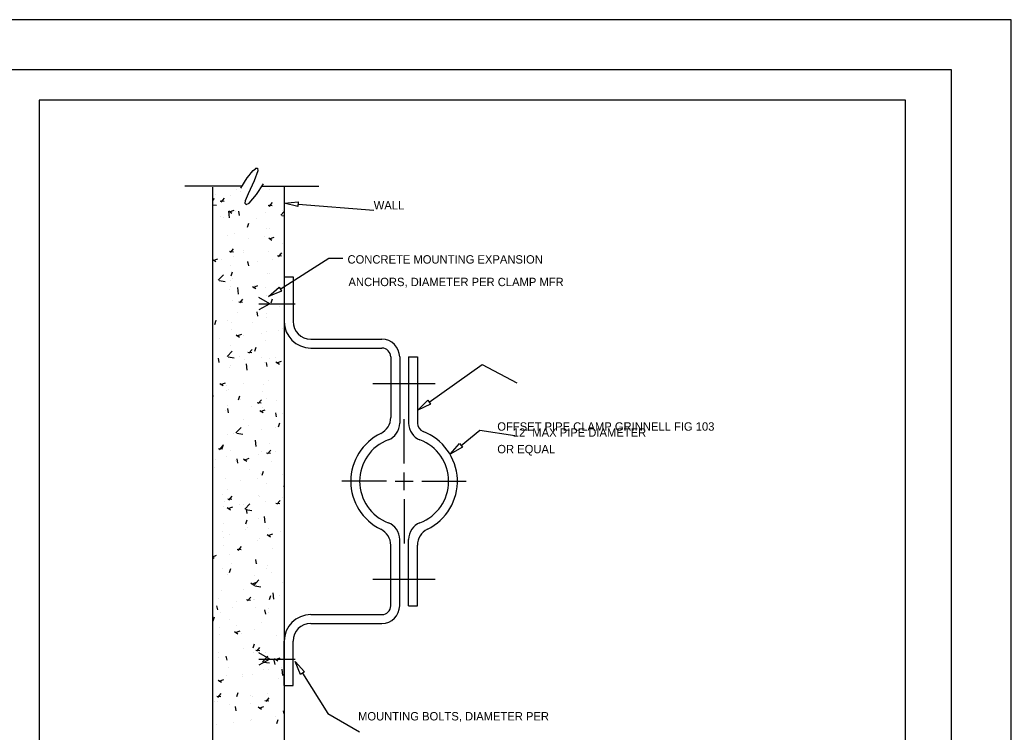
# Model space of a CAD drawing. Extents: x 2147138 to 2147698, y 2147153 to 2147515.
# Drawn here: x 2147555.6 to 2147697.7, y 2147412.9 to 2147515.1 of the extents above; entities that cross this region are included whole.
import ezdxf

# ---------------------------------------------------------------- set-up
doc = ezdxf.new("R2010")
doc.units = 0
for name, color, linetype in [('CONSTRUCTION_CLASS', 7, 'Continuous'), ('G-ANNO-TEXT-LW10', 7, 'Continuous'), ('G-DETL-CNTR', 7, 'Continuous'), ('G-DETL-HIDD', 7, 'Continuous'), ('G-DETL-LW20', 7, 'Continuous'), ('G-DETL-PATT', 7, 'Continuous'), ('PATTERN_CLASS', 7, 'Continuous')]:
    doc.layers.add(name, color=color, linetype=linetype)

msp = doc.modelspace()

# ---------------------------------------------------------------- linework, layer by layer
for p, q in [((2147588.42, 2147492.76), (2147588.72, 2147493.15)), ((2147588.72, 2147493.15), (2147589.02, 2147493.45)), ((2147589.02, 2147493.45), (2147589.32, 2147493.73)), ((2147589.68, 2147493.43), (2147589.15, 2147491.98)), ((2147589.32, 2147493.73), (2147589.34, 2147493.75)), ((2147589.34, 2147493.75), (2147589.38, 2147493.8)), ((2147589.38, 2147493.8), (2147589.64, 2147493.82)), ((2147589.64, 2147493.82), (2147589.68, 2147493.43)), ((2147587.22, 2147490.96), (2147588.14, 2147492.41)), ((2147588.14, 2147492.41), (2147588.42, 2147492.76)), ((2147589.15, 2147491.98), (2147588.28, 2147490.13)), ((2147587.4, 2147491.24), (2147579.2, 2147491.24)), ((2147588.28, 2147490.13), (2147587.84, 2147489.12)), ((2147589.48, 2147490.02), (2147590.51, 2147491.54)), ((2147590.31, 2147491.24), (2147598.4, 2147491.24)), ((2147587.84, 2147489.12), (2147587.82, 2147488.8)), ((2147587.82, 2147488.8), (2147588, 2147488.59)), ((2147588, 2147488.59), (2147588.44, 2147488.8)), ((2147588.44, 2147488.8), (2147589.48, 2147490.02))]:
    msp.add_line(p, q)
at = {"layer": 'CONSTRUCTION_CLASS'}
for p, q in [((2147697.66, 2147515.08), (2147137.79, 2147515.08)), ((2147697.66, 2147152.81), (2147697.66, 2147515.08)), ((2147160.2, 2147507.94), (2147689.06, 2147507.94)), ((2147689.06, 2147507.94), (2147689.06, 2147160.52))]:
    msp.add_line(p, q, dxfattribs=at)
at = {"layer": 'G-ANNO-TEXT-LW10'}
for p, q in [((2147595.44, 2147488.65), (2147606.32, 2147487.79)), ((2147592.89, 2147476.47), (2147599.87, 2147480.91)), ((2147599.87, 2147480.91), (2147601.87, 2147480.91)), ((2147614.24, 2147460.25), (2147621.83, 2147465.64)), ((2147621.83, 2147465.64), (2147626.79, 2147463.02)), ((2147618.8, 2147454.05), (2147621.49, 2147456.22)), ((2147621.49, 2147456.22), (2147626.52, 2147455.46)), ((2147596.08, 2147421.39), (2147599.71, 2147415.6)), ((2147599.71, 2147415.6), (2147604.24, 2147412.99))]:
    msp.add_line(p, q, dxfattribs=at)
for points in [[(2147595.41, 2147488.31), (2147593.45, 2147488.8), (2147595.47, 2147488.98)], [(2147593.07, 2147476.19), (2147591.21, 2147475.4), (2147592.72, 2147476.75)], [(2147614.44, 2147459.98), (2147612.61, 2147459.09), (2147614.05, 2147460.52)], [(2147619.01, 2147453.79), (2147617.24, 2147452.79), (2147618.59, 2147454.31)], [(2147595.8, 2147421.21), (2147595.02, 2147423.08), (2147596.37, 2147421.57)]]:
    msp.add_lwpolyline(points, close=True, dxfattribs=at)
at = {"layer": 'G-DETL-CNTR'}
for p, q in [((2147606.18, 2147462.91), (2147615.1, 2147462.91)), ((2147610.64, 2147451.44), (2147610.64, 2147457.81)), ((2147610.64, 2147447.62), (2147610.64, 2147450.17)), ((2147608.1, 2147448.9), (2147601.73, 2147448.9)), ((2147609.37, 2147448.9), (2147611.92, 2147448.9)), ((2147613.19, 2147448.9), (2147619.56, 2147448.9)), ((2147610.64, 2147446.35), (2147610.64, 2147439.98)), ((2147606.18, 2147434.88), (2147615.1, 2147434.88))]:
    msp.add_line(p, q, dxfattribs=at)
at = {"layer": 'G-DETL-HIDD'}
for p, q in [((2147591.39, 2147474.37), (2147589.83, 2147475.27)), ((2147589.83, 2147474.37), (2147595.03, 2147474.37)), ((2147591.39, 2147474.37), (2147589.83, 2147473.47)), ((2147591.39, 2147423.42), (2147589.83, 2147424.32)), ((2147591.39, 2147423.42), (2147589.83, 2147422.52)), ((2147589.83, 2147423.42), (2147595.03, 2147423.42))]:
    msp.add_line(p, q, dxfattribs=at)
at = {"layer": 'G-DETL-LW20'}
for p, q in [((2147583.21, 2147401.92), (2147583.21, 2147491.1)), ((2147593.45, 2147491.1), (2147593.45, 2147401.92)), ((2147593.45, 2147478.2), (2147593.45, 2147471.83)), ((2147593.45, 2147478.2), (2147594.72, 2147478.2)), ((2147594.72, 2147478.2), (2147594.72, 2147471.83)), ((2147597.27, 2147469.28), (2147607.46, 2147469.28)), ((2147597.27, 2147468), (2147607.46, 2147468)), ((2147608.73, 2147466.73), (2147608.73, 2147458.06)), ((2147610.01, 2147466.73), (2147610.01, 2147457.23)), ((2147611.28, 2147466.73), (2147612.55, 2147466.73)), ((2147611.28, 2147466.73), (2147611.28, 2147457.23)), ((2147612.55, 2147466.73), (2147612.55, 2147457.23)), ((2147610.01, 2147431.06), (2147610.01, 2147440.57)), ((2147611.28, 2147431.06), (2147611.28, 2147440.57)), ((2147608.73, 2147431.06), (2147608.73, 2147439.73)), ((2147612.55, 2147431.06), (2147612.55, 2147439.73)), ((2147611.28, 2147431.06), (2147612.55, 2147431.06)), ((2147597.27, 2147429.79), (2147607.46, 2147429.79)), ((2147597.27, 2147428.52), (2147607.46, 2147428.52)), ((2147593.45, 2147419.6), (2147593.45, 2147425.97)), ((2147594.72, 2147419.6), (2147594.72, 2147425.97)), ((2147593.45, 2147419.6), (2147594.72, 2147419.6))]:
    msp.add_line(p, q, dxfattribs=at)
for centre, radius, start, end in [((2147597.27, 2147471.83), 3.82, 180, 270), ((2147597.27, 2147471.83), 2.55, 180, 270), ((2147607.46, 2147466.73), 2.55, 0, 90), ((2147607.46, 2147466.73), 1.27, 0, 90), ((2147606.18, 2147458.06), 2.55, 295.9445, 0), ((2147607.46, 2147457.23), 2.55, 290.9248, 0), ((2147613.83, 2147457.23), 2.55, 180, 249.0752), ((2147613.83, 2147457.23), 1.27, 180, 249.0752), ((2147610.64, 2147448.9), 7.64, 295.9445, 69.0752), ((2147610.64, 2147448.9), 7.64, 115.9445, 244.0555), ((2147610.64, 2147448.9), 6.37, 110.9248, 249.0752), ((2147610.64, 2147448.9), 6.37, 290.9248, 69.0752), ((2147606.18, 2147439.73), 2.55, 0, 64.0555), ((2147607.46, 2147440.57), 2.55, 0, 69.0752), ((2147613.83, 2147440.57), 2.55, 110.9248, 180), ((2147615.1, 2147439.73), 2.55, 115.9445, 180), ((2147607.46, 2147431.06), 2.55, 270, 0), ((2147607.46, 2147431.06), 1.27, 270, 0), ((2147597.27, 2147425.97), 3.82, 90, 180), ((2147597.27, 2147425.97), 2.55, 90, 180)]:
    msp.add_arc(centre, radius, start, end, dxfattribs=at)
at = {"layer": 'G-DETL-PATT'}
for p, q in [((2147586.56, 2147490.79), (2147586.56, 2147490.79)), ((2147587.25, 2147490.47), (2147587.25, 2147490.47)), ((2147591.37, 2147490.81), (2147591.37, 2147490.81)), ((2147593.41, 2147490.22), (2147593.41, 2147490.22)), ((2147583.21, 2147489.19), (2147583.46, 2147489.45)), ((2147583.62, 2147489.99), (2147583.62, 2147489.99)), ((2147584.27, 2147489.1), (2147584.84, 2147489.05)), ((2147584.41, 2147488.93), (2147584.88, 2147489.48)), ((2147585.77, 2147489.85), (2147585.77, 2147489.85)), ((2147591.3, 2147488.33), (2147591.76, 2147488.88)), ((2147583.21, 2147488.57), (2147583.73, 2147488.49)), ((2147585.5, 2147487.69), (2147585.97, 2147487.37)), ((2147585.62, 2147486.7), (2147585.51, 2147487.62)), ((2147585.63, 2147487.53), (2147586.3, 2147487.79)), ((2147586.44, 2147487.59), (2147586.44, 2147487.59)), ((2147587.04, 2147487.02), (2147586.93, 2147487.62)), ((2147590.79, 2147487.48), (2147590.79, 2147487.48)), ((2147591.15, 2147488.5), (2147591.72, 2147488.45)), ((2147591.43, 2147488.31), (2147591.43, 2147488.31)), ((2147592.96, 2147487.08), (2147593.45, 2147487.59)), ((2147593.19, 2147487.8), (2147593.19, 2147487.8)), ((2147584.35, 2147486.85), (2147584.35, 2147486.85)), ((2147584.73, 2147486.68), (2147584.73, 2147486.68)), ((2147588.18, 2147485.34), (2147588.37, 2147485.92)), ((2147589.47, 2147486.63), (2147589.47, 2147486.63)), ((2147593.12, 2147487.04), (2147593.45, 2147486.99)), ((2147590.97, 2147485.09), (2147590.97, 2147485.09)), ((2147591.31, 2147485.12), (2147591.31, 2147485.12)), ((2147585.37, 2147484.12), (2147585.37, 2147484.12)), ((2147586.33, 2147484.4), (2147586.33, 2147484.4)), ((2147588.27, 2147483.69), (2147588.27, 2147483.69)), ((2147590.67, 2147484.01), (2147590.67, 2147484.01)), ((2147591.23, 2147483.82), (2147591.7, 2147483.5)), ((2147591.36, 2147483.66), (2147592.03, 2147483.92)), ((2147585.6, 2147481.88), (2147586.17, 2147481.83)), ((2147585.75, 2147481.71), (2147586.21, 2147482.26)), ((2147587.6, 2147481.73), (2147587.6, 2147481.73)), ((2147587.67, 2147482.02), (2147587.67, 2147482.02)), ((2147591.2, 2147481.92), (2147591.2, 2147481.92)), ((2147592.63, 2147481.1), (2147593.1, 2147481.66)), ((2147593.27, 2147482.98), (2147593.27, 2147482.98)), ((2147583.21, 2147480.69), (2147583.64, 2147480.4)), ((2147583.29, 2147480.57), (2147583.96, 2147480.82)), ((2147584.5, 2147480.65), (2147584.5, 2147480.65)), ((2147586.21, 2147481.2), (2147586.21, 2147481.2)), ((2147588.14, 2147480.22), (2147588.14, 2147480.22)), ((2147588.37, 2147479.79), (2147588.26, 2147480.4)), ((2147589.63, 2147480.44), (2147589.63, 2147480.44)), ((2147591.78, 2147480.7), (2147591.78, 2147480.7)), ((2147592.48, 2147481.28), (2147593.06, 2147481.23)), ((2147592.73, 2147481.51), (2147592.73, 2147481.51)), ((2147585.74, 2147479.91), (2147585.74, 2147479.91)), ((2147585.84, 2147478.37), (2147586.04, 2147478.95)), ((2147583.99, 2147477.73), (2147584.74, 2147478.51)), ((2147584.15, 2147477.69), (2147585, 2147477.55)), ((2147585.74, 2147477.7), (2147585.74, 2147477.7)), ((2147586.09, 2147478), (2147586.09, 2147478)), ((2147591.08, 2147478.72), (2147591.08, 2147478.72)), ((2147591.34, 2147478.66), (2147591.34, 2147478.66)), ((2147583.22, 2147476.12), (2147583.22, 2147476.12)), ((2147585.62, 2147476.44), (2147585.62, 2147476.44)), ((2147585.69, 2147476.85), (2147585.69, 2147476.85)), ((2147586.89, 2147475.76), (2147586.79, 2147476.68)), ((2147588.89, 2147476.86), (2147589.37, 2147476.54)), ((2147589.02, 2147476.7), (2147589.69, 2147476.96)), ((2147589.25, 2147476.91), (2147589.25, 2147476.91)), ((2147590.82, 2147476.63), (2147590.82, 2147476.63)), ((2147585.98, 2147474.81), (2147585.98, 2147474.81)), ((2147586.93, 2147474.66), (2147587.5, 2147474.61)), ((2147587.08, 2147474.49), (2147587.54, 2147475.04)), ((2147590.96, 2147475.53), (2147590.96, 2147475.53)), ((2147591.57, 2147474.51), (2147591.77, 2147475.09)), ((2147586.73, 2147473.13), (2147586.73, 2147473.13)), ((2147589.7, 2147472.57), (2147589.59, 2147473.18)), ((2147592.79, 2147473.93), (2147592.79, 2147473.93)), ((2147583.51, 2147471.41), (2147583.7, 2147471.99)), ((2147583.82, 2147471.94), (2147583.82, 2147471.94)), ((2147585.35, 2147471.97), (2147585.35, 2147471.97)), ((2147588.95, 2147471.73), (2147588.95, 2147471.73)), ((2147590.85, 2147472.33), (2147590.85, 2147472.33)), ((2147590.94, 2147472.93), (2147590.94, 2147472.93)), ((2147585.85, 2147470.65), (2147585.85, 2147470.65)), ((2147585.86, 2147471.61), (2147585.86, 2147471.61)), ((2147590.97, 2147470.44), (2147590.97, 2147470.44)), ((2147592.67, 2147470.46), (2147592.67, 2147470.46)), ((2147593.24, 2147470.82), (2147593.24, 2147470.82)), ((2147584.2, 2147469.34), (2147584.2, 2147469.34)), ((2147586.55, 2147469.9), (2147587.03, 2147469.58)), ((2147586.69, 2147469.74), (2147587.36, 2147470)), ((2147587.65, 2147469.86), (2147587.65, 2147469.86)), ((2147590.27, 2147470.14), (2147590.27, 2147470.14)), ((2147590.73, 2147469.14), (2147590.73, 2147469.14)), ((2147585.26, 2147466.79), (2147586.01, 2147467.57)), ((2147585.74, 2147468.42), (2147585.74, 2147468.42)), ((2147588.26, 2147467.44), (2147588.84, 2147467.39)), ((2147588.41, 2147467.27), (2147588.87, 2147467.82)), ((2147589.24, 2147467.55), (2147589.43, 2147468.13)), ((2147584.15, 2147465.95), (2147584.04, 2147466.56)), ((2147585.42, 2147466.75), (2147586.27, 2147466.61)), ((2147587.04, 2147466.85), (2147587.04, 2147466.85)), ((2147587.74, 2147466.35), (2147587.74, 2147466.35)), ((2147590.14, 2147466.67), (2147590.14, 2147466.67)), ((2147591.31, 2147466.5), (2147591.31, 2147466.5)), ((2147592.16, 2147466.63), (2147592.16, 2147466.63)), ((2147592.28, 2147466.03), (2147592.76, 2147465.71)), ((2147592.42, 2147465.87), (2147593.09, 2147466.13)), ((2147585.63, 2147465.22), (2147585.63, 2147465.22)), ((2147585.71, 2147465.54), (2147585.71, 2147465.54)), ((2147588.17, 2147464.82), (2147588.06, 2147465.73)), ((2147590.61, 2147465.94), (2147590.61, 2147465.94)), ((2147591.03, 2147465.35), (2147590.92, 2147465.95)), ((2147591.25, 2147463.36), (2147591.25, 2147463.36)), ((2147584.22, 2147462.94), (2147584.7, 2147462.62)), ((2147584.35, 2147462.78), (2147585.02, 2147463.04)), ((2147585.17, 2147461.94), (2147585.17, 2147461.94)), ((2147585.22, 2147462.57), (2147585.22, 2147462.57)), ((2147585.51, 2147462.02), (2147585.51, 2147462.02)), ((2147587.62, 2147462.88), (2147587.62, 2147462.88)), ((2147590.29, 2147461.72), (2147590.29, 2147461.72)), ((2147590.5, 2147462.74), (2147590.5, 2147462.74)), ((2147583.21, 2147461.07), (2147583.32, 2147461.2)), ((2147583.21, 2147460.77), (2147583.28, 2147460.77)), ((2147586.9, 2147460.59), (2147587.09, 2147461.17)), ((2147587.19, 2147460.65), (2147587.19, 2147460.65)), ((2147589.74, 2147460.04), (2147590.21, 2147460.6)), ((2147590.92, 2147460.77), (2147590.92, 2147460.77)), ((2147592.32, 2147460.43), (2147592.32, 2147460.43)), ((2147585.09, 2147459.1), (2147585.09, 2147459.1)), ((2147585.32, 2147459.81), (2147585.32, 2147459.81)), ((2147585.48, 2147458.73), (2147585.37, 2147459.34)), ((2147588.73, 2147459.58), (2147588.73, 2147459.58)), ((2147589.59, 2147460.21), (2147590.17, 2147460.16)), ((2147589.95, 2147459.07), (2147590.43, 2147458.75)), ((2147590.08, 2147458.91), (2147590.75, 2147459.17)), ((2147590.38, 2147459.55), (2147590.38, 2147459.55)), ((2147585.39, 2147458.83), (2147585.39, 2147458.83)), ((2147587.62, 2147457.7), (2147587.62, 2147457.7)), ((2147592.37, 2147458.13), (2147592.26, 2147458.73)), ((2147593.22, 2147458.67), (2147593.22, 2147458.67)), ((2147583.26, 2147457.06), (2147583.26, 2147457.06)), ((2147586.53, 2147455.85), (2147587.28, 2147456.63)), ((2147588.38, 2147456.84), (2147588.38, 2147456.84)), ((2147590.26, 2147456.35), (2147590.26, 2147456.35)), ((2147592.27, 2147456.59), (2147592.27, 2147456.59)), ((2147592.63, 2147456.72), (2147592.82, 2147457.3)), ((2147585.28, 2147455.63), (2147585.28, 2147455.63)), ((2147586.2, 2147455.79), (2147586.2, 2147455.79)), ((2147586.69, 2147455.81), (2147587.54, 2147455.67)), ((2147589.44, 2147453.88), (2147589.33, 2147454.79)), ((2147584.04, 2147453.6), (2147584.61, 2147453.55)), ((2147584.19, 2147453.43), (2147584.65, 2147453.98)), ((2147584.56, 2147453.62), (2147584.76, 2147454.2)), ((2147585.69, 2147453.38), (2147585.69, 2147453.38)), ((2147591.07, 2147452.82), (2147591.54, 2147453.37)), ((2147591.28, 2147454.34), (2147591.28, 2147454.34)), ((2147583.68, 2147452), (2147583.68, 2147452)), ((2147585.16, 2147452.44), (2147585.16, 2147452.44)), ((2147586.51, 2147451.94), (2147586.51, 2147451.94)), ((2147586.81, 2147451.51), (2147586.7, 2147452.11)), ((2147587.61, 2147452.11), (2147588.09, 2147451.79)), ((2147587.74, 2147451.95), (2147588.42, 2147452.21)), ((2147589.74, 2147452.8), (2147589.74, 2147452.8)), ((2147590.15, 2147453.16), (2147590.15, 2147453.16)), ((2147590.93, 2147452.99), (2147591.5, 2147452.94)), ((2147592.14, 2147453.12), (2147592.14, 2147453.12)), ((2147583.41, 2147450.87), (2147583.41, 2147450.87)), ((2147588.54, 2147450.65), (2147588.54, 2147450.65)), ((2147591.64, 2147451.72), (2147591.64, 2147451.72)), ((2147585.04, 2147449.24), (2147585.04, 2147449.24)), ((2147587.22, 2147449.02), (2147587.22, 2147449.02)), ((2147589.62, 2147449.33), (2147589.62, 2147449.33)), ((2147590.03, 2147449.96), (2147590.03, 2147449.96)), ((2147590.29, 2147449.76), (2147590.49, 2147450.34)), ((2147593.25, 2147449.81), (2147593.25, 2147449.81)), ((2147585.29, 2147447.66), (2147585.29, 2147447.66)), ((2147590.89, 2147448.62), (2147590.89, 2147448.62)), ((2147593.34, 2147448.25), (2147593.45, 2147448.18)), ((2147584.6, 2147447.06), (2147584.6, 2147447.06)), ((2147585.37, 2147446.37), (2147585.95, 2147446.32)), ((2147585.52, 2147446.2), (2147585.98, 2147446.76)), ((2147589.73, 2147446.84), (2147589.73, 2147446.84)), ((2147589.91, 2147446.77), (2147589.91, 2147446.77)), ((2147592.41, 2147445.6), (2147592.87, 2147446.15)), ((2147593.19, 2147446.51), (2147593.19, 2147446.51)), ((2147584.69, 2147445.23), (2147584.69, 2147445.23)), ((2147584.93, 2147446.05), (2147584.93, 2147446.05)), ((2147585.28, 2147445.15), (2147585.75, 2147444.83)), ((2147585.41, 2147444.99), (2147586.08, 2147445.25)), ((2147587.09, 2147445.55), (2147587.09, 2147445.55)), ((2147587.59, 2147445.55), (2147587.59, 2147445.55)), ((2147587.81, 2147444.91), (2147588.55, 2147445.69)), ((2147587.96, 2147444.87), (2147588.82, 2147444.73)), ((2147588.14, 2147444.29), (2147588.03, 2147444.89)), ((2147590.73, 2147446.02), (2147590.73, 2147446.02)), ((2147592.26, 2147445.77), (2147592.83, 2147445.72)), ((2147587.96, 2147442.8), (2147588.15, 2147443.38)), ((2147589.79, 2147443.57), (2147589.79, 2147443.57)), ((2147590.71, 2147442.94), (2147590.61, 2147443.85)), ((2147584.81, 2147442.85), (2147584.81, 2147442.85)), ((2147587.86, 2147441.94), (2147587.86, 2147441.94)), ((2147588.2, 2147442.24), (2147588.2, 2147442.24)), ((2147591.26, 2147442.19), (2147591.26, 2147442.19)), ((2147584.57, 2147441.76), (2147584.57, 2147441.76)), ((2147584.76, 2147440.86), (2147584.76, 2147440.86)), ((2147585.66, 2147441.23), (2147585.66, 2147441.23)), ((2147589.88, 2147440.65), (2147589.88, 2147440.65)), ((2147591.01, 2147441.29), (2147591.49, 2147440.96)), ((2147591.14, 2147441.12), (2147591.81, 2147441.38)), ((2147592.98, 2147441.72), (2147592.98, 2147441.72)), ((2147584.69, 2147439.65), (2147584.69, 2147439.65)), ((2147586.7, 2147439.15), (2147587.28, 2147439.1)), ((2147586.85, 2147438.98), (2147587.32, 2147439.53)), ((2147589.68, 2147440.37), (2147589.68, 2147440.37)), ((2147591.74, 2147439.25), (2147591.74, 2147439.25)), ((2147583.21, 2147438.08), (2147583.75, 2147438.29)), ((2147583.21, 2147438), (2147583.42, 2147437.87)), ((2147585.68, 2147438.45), (2147585.68, 2147438.45)), ((2147589.48, 2147437.07), (2147589.37, 2147437.67)), ((2147584.58, 2147436.46), (2147584.58, 2147436.46)), ((2147585.62, 2147435.84), (2147585.82, 2147436.42)), ((2147585.95, 2147437.06), (2147585.95, 2147437.06)), ((2147589.56, 2147437.18), (2147589.56, 2147437.18)), ((2147590.86, 2147436.46), (2147590.86, 2147436.46)), ((2147591.07, 2147436.84), (2147591.07, 2147436.84)), ((2147585.26, 2147435.5), (2147585.26, 2147435.5)), ((2147589.08, 2147433.97), (2147589.83, 2147434.75)), ((2147589.22, 2147435.46), (2147589.22, 2147435.46)), ((2147591.62, 2147435.78), (2147591.62, 2147435.78)), ((2147587.56, 2147433.39), (2147587.56, 2147433.39)), ((2147588.67, 2147434.32), (2147589.15, 2147434)), ((2147588.8, 2147434.16), (2147589.48, 2147434.42)), ((2147589.24, 2147433.92), (2147590.09, 2147433.79)), ((2147589.44, 2147433.98), (2147589.44, 2147433.98)), ((2147593.16, 2147434.35), (2147593.16, 2147434.35)), ((2147584.08, 2147432.15), (2147584.08, 2147432.15)), ((2147584.46, 2147433.26), (2147584.46, 2147433.26)), ((2147588.04, 2147431.93), (2147588.61, 2147431.88)), ((2147588.19, 2147431.76), (2147588.65, 2147432.31)), ((2147589.09, 2147431.99), (2147589.09, 2147431.99)), ((2147589.2, 2147431.93), (2147589.2, 2147431.93)), ((2147591.35, 2147431.97), (2147591.55, 2147432.55)), ((2147591.98, 2147432), (2147591.88, 2147432.91)), ((2147592.73, 2147432.47), (2147592.73, 2147432.47)), ((2147583.92, 2147430.45), (2147583.81, 2147431.05)), ((2147586.1, 2147430.86), (2147586.1, 2147430.86)), ((2147586.69, 2147431.68), (2147586.69, 2147431.68)), ((2147589.33, 2147430.79), (2147589.33, 2147430.79)), ((2147590.81, 2147429.85), (2147590.7, 2147430.45)), ((2147591.23, 2147430.65), (2147591.23, 2147430.65)), ((2147583.29, 2147428.87), (2147583.48, 2147429.45)), ((2147584.34, 2147430.07), (2147584.34, 2147430.07)), ((2147585.63, 2147429.07), (2147585.63, 2147429.07)), ((2147591.23, 2147430.03), (2147591.23, 2147430.03)), ((2147584.16, 2147427.89), (2147584.16, 2147427.89)), ((2147586.57, 2147428.21), (2147586.57, 2147428.21)), ((2147590.2, 2147428.69), (2147590.2, 2147428.69)), ((2147584.23, 2147426.87), (2147584.23, 2147426.87)), ((2147586.34, 2147427.36), (2147586.81, 2147427.04)), ((2147586.47, 2147427.2), (2147587.14, 2147427.46)), ((2147587.29, 2147427.05), (2147587.29, 2147427.05)), ((2147589.21, 2147427.59), (2147589.21, 2147427.59)), ((2147592.42, 2147426.84), (2147592.42, 2147426.84)), ((2147587.68, 2147424.9), (2147587.68, 2147424.9)), ((2147589.02, 2147425.01), (2147589.21, 2147425.59)), ((2147589.52, 2147424.54), (2147589.98, 2147425.09)), ((2147584.04, 2147424.42), (2147584.04, 2147424.42)), ((2147584.11, 2147423.68), (2147584.11, 2147423.68)), ((2147585.26, 2147423.23), (2147585.14, 2147423.83)), ((2147585.23, 2147423.34), (2147585.23, 2147423.34)), ((2147589.09, 2147424.4), (2147589.09, 2147424.4)), ((2147589.37, 2147424.71), (2147589.94, 2147424.66)), ((2147590.35, 2147423.03), (2147591.1, 2147423.81)), ((2147590.83, 2147424.3), (2147590.83, 2147424.3)), ((2147592.07, 2147423.5), (2147592.54, 2147423.18)), ((2147592.2, 2147423.34), (2147592.87, 2147423.59)), ((2147585.43, 2147422.15), (2147585.43, 2147422.15)), ((2147590.51, 2147422.98), (2147591.36, 2147422.85)), ((2147590.55, 2147421.93), (2147590.55, 2147421.93)), ((2147592.14, 2147422.63), (2147592.03, 2147423.23)), ((2147593.13, 2147422.2), (2147593.13, 2147422.2)), ((2147593.26, 2147421.06), (2147593.15, 2147421.97)), ((2147585.15, 2147421.11), (2147585.15, 2147421.11)), ((2147587.45, 2147420.86), (2147587.45, 2147420.86)), ((2147587.53, 2147421.24), (2147587.53, 2147421.24)), ((2147588.98, 2147421.2), (2147588.98, 2147421.2)), ((2147591.22, 2147421.91), (2147591.22, 2147421.91)), ((2147592.57, 2147420.64), (2147592.57, 2147420.64)), ((2147583.99, 2147420.48), (2147583.99, 2147420.48)), ((2147584, 2147420.4), (2147584.48, 2147420.08)), ((2147584.13, 2147420.24), (2147584.8, 2147420.5)), ((2147583.81, 2147418.09), (2147584.39, 2147418.04)), ((2147583.96, 2147417.92), (2147584.43, 2147418.47)), ((2147586.68, 2147418.05), (2147586.88, 2147418.63)), ((2147588.69, 2147418.12), (2147588.69, 2147418.12)), ((2147588.86, 2147418), (2147588.86, 2147418)), ((2147590.85, 2147417.32), (2147591.31, 2147417.87)), ((2147591.09, 2147418.44), (2147591.09, 2147418.44)), ((2147591.2, 2147417.88), (2147591.2, 2147417.88)), ((2147583.52, 2147417.27), (2147583.52, 2147417.27)), ((2147583.87, 2147417.28), (2147583.87, 2147417.28)), ((2147585.6, 2147416.91), (2147585.6, 2147416.91)), ((2147586.59, 2147416.01), (2147586.48, 2147416.61)), ((2147588.64, 2147417.05), (2147588.64, 2147417.05)), ((2147589.73, 2147416.54), (2147590.21, 2147416.21)), ((2147589.86, 2147416.38), (2147590.53, 2147416.63)), ((2147590.7, 2147417.49), (2147591.27, 2147417.44)), ((2147592.2, 2147415.13), (2147592.2, 2147415.13)), ((2147593.45, 2147415.55), (2147593.36, 2147416.01)), ((2147583.76, 2147414.09), (2147583.76, 2147414.09)), ((2147586.16, 2147414.34), (2147586.16, 2147414.34)), ((2147588.57, 2147414.65), (2147588.57, 2147414.65)), ((2147588.74, 2147414.81), (2147588.74, 2147414.81)), ((2147592.41, 2147414.18), (2147592.61, 2147414.76))]:
    msp.add_line(p, q, dxfattribs=at)
at = {"layer": 'PATTERN_CLASS'}
for p, q in [((2147682.5, 2147503.54), (2147558.31, 2147503.54)), ((2147558.31, 2147503.54), (2147558.31, 2147351.27)), ((2147682.5, 2147351.27), (2147682.5, 2147503.54))]:
    msp.add_line(p, q, dxfattribs=at)

# ---------------------------------------------------------------- texts
at = {"layer": 'G-ANNO-TEXT-LW10'}
for s, p in [('WALL', (2147606.29, 2147487.88)), ('CONCRETE MOUNTING EXPANSION', (2147602.53, 2147480.12)), ('ANCHORS, DIAMETER PER CLAMP MFR', (2147602.67, 2147476.89)), ('OFFSET PIPE CLAMP GRINNELL FIG 103', (2147624, 2147456.16)), ('12" MAX PIPE DIAMETER', (2147626.22, 2147455.3)), ('OR EQUAL', (2147624, 2147452.92)), ('MOUNTING BOLTS, DIAMETER PER', (2147604.04, 2147414.61))]:
    msp.add_text(s, height=1.2, dxfattribs=at).set_placement(p)

doc.saveas('drawing.dxf')
